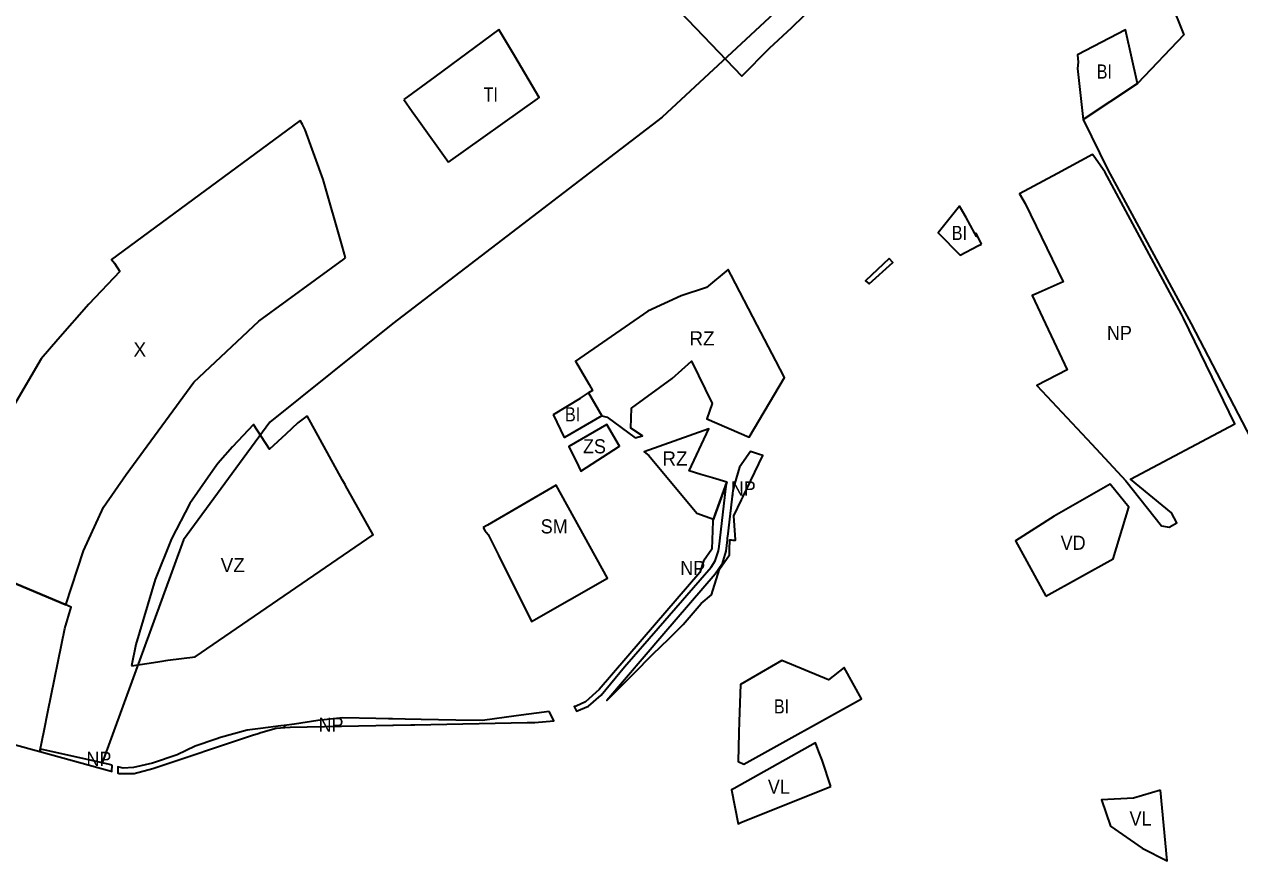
# Model space of a CAD drawing. Extents: x -650276 to -642489, y -1074311 to -1066658.
# Drawn here: x -647227 to -646196, y -1073134 to -1072424 of the extents above; entities that cross this region are included whole.
import ezdxf

# ---------------------------------------------------------------- set-up
doc = ezdxf.new("R2010")
doc.units = 0
doc.header["$LTSCALE"] = 4.8
for name, color, linetype, lineweight in [('18', 7, 'Continuous', 35), ('2', 7, 'Continuous', 35), ('30', 7, 'Continuous', 35), ('34', 7, 'Continuous', 35), ('35', 7, 'Continuous', 35), ('36', 7, 'Continuous', 35), ('41', 7, 'Continuous', 35), ('42', 7, 'Continuous', 35), ('48', 7, 'Continuous', 35), ('51', 7, 'Continuous', 35), ('54', 7, 'Continuous', 35), ('6', 7, 'Continuous', 35), ('61', 7, 'Continuous', 25)]:
    doc.layers.add(name, color=color, linetype=linetype, lineweight=lineweight)
doc.layers.add('62', color=7, linetype='Continuous')
doc.layers.add('63', color=7, linetype='Continuous')

msp = doc.modelspace()

# ---------------------------------------------------------------- linework, layer by layer
at = {"layer": '18'}
msp.add_lwpolyline([(-646837.81, -1072851.3), (-646836.5, -1072853.76), (-646833.67, -1072857.15), (-646824.89, -1072874.66), (-646796.68, -1072930.92), (-646732.28, -1072894.29), (-646775.85, -1072815.39), (-646834.08, -1072849.15)], close=True, dxfattribs=at)
at = {"layer": '2'}
msp.add_line((-646417.787, -1072612.168), (-646414.77, -1072610.61), dxfattribs=at)
for points in [[(-646333.34, -1072461.67), (-646328.45, -1072504.81), (-646282.47, -1072474.34), (-646292.44, -1072428.89), (-646333.33, -1072450.12), (-646332.68, -1072456.19)], [(-646778.2, -1072755.19), (-646755.1, -1072741.28), (-646748.3, -1072737.01), (-646737.05, -1072756.4), (-646768.74, -1072774.78)], [(-646620.38, -1073015.9), (-646620.71, -1073025.49), (-646621.44, -1073049.79), (-646616.55, -1073052.21), (-646516.7, -1072996.65), (-646531.46, -1072970.12), (-646544.68, -1072980.62), (-646584.23, -1072964.22), (-646619.48, -1072984.34)]]:
    msp.add_lwpolyline(points, close=True, dxfattribs=at)
for points in [[(-646420.36, -1072601.78), (-646427.95, -1072588.07), (-646432.57, -1072579.75), (-646433.36, -1072578.45), (-646451.458, -1072601.008), (-646433.024, -1072620.04), (-646417.787, -1072612.168)], [(-646414.77, -1072610.61), (-646419.11, -1072602.03), (-646419.47, -1072601.31), (-646419.02, -1072604.18), (-646420.36, -1072601.78)]]:
    msp.add_lwpolyline(points, dxfattribs=at)
at = {"layer": '30'}
for points in [[(-646824.42, -1072428.58), (-646878.91, -1072468.54), (-646905.18, -1072487.8)], [(-646867.283, -1072540.984), (-646791.569, -1072487.198), (-646790.354, -1072486.136), (-646810.77, -1072451.09), (-646824.42, -1072428.58)], [(-646905.18, -1072487.8), (-646898.1, -1072498.02), (-646893.64, -1072504.45), (-646867.283, -1072540.984)]]:
    msp.add_lwpolyline(points, dxfattribs=at)
at = {"layer": '34'}
msp.add_lwpolyline([(-646542.62, -1073071.1), (-646550.01, -1073048.55), (-646552.79, -1073041.53), (-646555.79, -1073033.92), (-646624.69, -1073072.66), (-646626.967, -1073073.918), (-646621.38, -1073102.66), (-646620.19, -1073102.14), (-646618.56, -1073101.42)], close=True, dxfattribs=at)
msp.add_lwpolyline([(-646542.62, -1073071.1), (-646550.01, -1073048.55), (-646552.79, -1073041.53), (-646555.79, -1073033.92), (-646624.69, -1073072.66), (-646626.967, -1073073.918), (-646621.38, -1073102.66), (-646620.19, -1073102.14), (-646618.56, -1073101.42)], close=True, dxfattribs=at)
for points in [[(-646262.94, -1073074.15), (-646285.77, -1073081.01), (-646312.87, -1073082.4), (-646305.18, -1073104.8), (-646278.38, -1073123.25)], [(-646262.94, -1073074.15), (-646285.77, -1073081.01), (-646312.87, -1073082.4), (-646305.18, -1073104.8), (-646278.38, -1073123.25)], [(-646278.38, -1073123.25), (-646257.09, -1073134.01), (-646262.94, -1073074.15)], [(-646278.38, -1073123.25), (-646257.09, -1073134.01), (-646262.94, -1073074.15)]]:
    msp.add_lwpolyline(points, dxfattribs=at)
at = {"layer": '35'}
msp.add_lwpolyline([(-646360.22, -1072909.57), (-646303.02, -1072877.74), (-646289.63, -1072834.04), (-646305.56, -1072814.43), (-646353.25, -1072841.63), (-646385.86, -1072862.59)], close=True, dxfattribs=at)
at = {"layer": '36'}
for points in [[(-646987.154, -1072756.377), (-646995.02, -1072762.45), (-647005.249, -1072771.938), (-647019.06, -1072784.57), (-647032.7, -1072763.68), (-647050.492, -1072782.771)], [(-646954.7, -1072815.232), (-646957.105, -1072810.92), (-646987.154, -1072756.377)], [(-647050.492, -1072782.771), (-647063.04, -1072796.74), (-647067.22, -1072802.77), (-647086.65, -1072830.76), (-647102.38, -1072860.7), (-647116.33, -1072895.3)], [(-647136.39, -1072968.63), (-647110.32, -1072964.56), (-647107.01, -1072964.04), (-647105.4, -1072963.84), (-647082.36, -1072960.95), (-646931.1, -1072857.55), (-646954.51, -1072815.63), (-646954.7, -1072815.232)], [(-647116.33, -1072895.3), (-647132.47, -1072950.4), (-647136.39, -1072968.63)]]:
    msp.add_lwpolyline(points, dxfattribs=at)
at = {"layer": '41'}
msp.add_lwpolyline([(-646756.92, -1072799.26), (-646754.96, -1072803.29), (-646722.072, -1072782.236), (-646732.76, -1072763.81), (-646765, -1072782.52)], close=True, dxfattribs=at)
at = {"layer": '42'}
msp.add_lwpolyline([(-646696.83, -1072385.81), (-646618.158, -1072468.098), (-646594.606, -1072444.422), (-646575.792, -1072426.789), (-646504.244, -1072357.026)], dxfattribs=at)
at = {"layer": '48'}
msp.add_line((-646779.55, -1073011.68), (-646781.703, -1073007.452), dxfattribs=at)
for points in [[(-646194.19, -1072404.62), (-646254.75, -1072404.25), (-646243.17, -1072432.88), (-646282.47, -1072474.34), (-646328.45, -1072504.81), (-646307.6, -1072547.74), (-646236.97, -1072678.31), (-646171.72, -1072803.51)], [(-646918.156, -1073013.511), (-646928.807, -1073013.313), (-646956.919, -1073012.775), (-646978.077, -1073014.931), (-646997.824, -1073018.092), (-647006.715, -1073019.236), (-647006.15, -1073020.99), (-647001.66, -1073020.72), (-646914.54, -1073019)], [(-646781.703, -1073007.452), (-646809.778, -1073011.019), (-646838.25, -1073014.938), (-646861.07, -1073014.672), (-646890.523, -1073014.073), (-646904.131, -1073013.793), (-646914.796, -1073013.573), (-646918.156, -1073013.511)], [(-646800.44, -1073016.74), (-646793.8, -1073016.61), (-646777.74, -1073015.29), (-646779.55, -1073011.68)], [(-646914.54, -1073019), (-646913.94, -1073018.99), (-646899.22, -1073018.7), (-646895.76, -1073018.63), (-646800.44, -1073016.74)]]:
    msp.add_lwpolyline(points, dxfattribs=at)
for points in [[(-646310.01, -1072549.22), (-646319.56, -1072536.05), (-646320.62, -1072534.6), (-646350.18, -1072550.59), (-646382.41, -1072568.01), (-646377.84, -1072576.29), (-646345.6, -1072642.55), (-646368.51, -1072652.81), (-646371.66, -1072654.2), (-646342.08, -1072717.43), (-646367.72, -1072730.68), (-646321.171, -1072780.535), (-646292.17, -1072811.6), (-646261.97, -1072849.66), (-646255.39, -1072850.83), (-646249.04, -1072847.16), (-646253.56, -1072838.8), (-646288.27, -1072810.22), (-646199.72, -1072763.1), (-646243.32, -1072673.57), (-646245.13, -1072670.2), (-646278.44, -1072608.07)], [(-646493.229, -1072622.74), (-646513.209, -1072641.935), (-646510.28, -1072644.42), (-646490.11, -1072626.15)], [(-646644.059, -1072908.208), (-646637.2, -1072886.57), (-646628.7, -1072874.5), (-646628.58, -1072869.88), (-646628.36, -1072861.71), (-646627.159, -1072861.792), (-646625.96, -1072861.874), (-646625.3, -1072861.919), (-646624.824, -1072861.951), (-646623.67, -1072862.024), (-646623.712, -1072861.37), (-646623.95, -1072857.6), (-646625.02, -1072841.21), (-646618.521, -1072827.719), (-646617.407, -1072825.407), (-646614.07, -1072818.47), (-646600.37, -1072790.04), (-646603.99, -1072788.901), (-646610.86, -1072786.74), (-646620.27, -1072799.95), (-646624.54, -1072814.52), (-646625.91, -1072819.66), (-646630.45, -1072858.93), (-646630.57, -1072859.99), (-646630.76, -1072861.61), (-646631.89, -1072871.33), (-646635.11, -1072882.47), (-646640.96, -1072890.83), (-646684.36, -1072941.43), (-646732.95, -1072998.07), (-646710.3, -1072975.31), (-646693.9, -1072958.84), (-646680.07, -1072945.74), (-646668.09, -1072933.43), (-646652.76, -1072915.66), (-646644.069, -1072908.218), (-646644.061, -1072908.209)], [(-646642.438, -1072844.29), (-646642.939, -1072845.68), (-646643.574, -1072869.57), (-646650.798, -1072879.828), (-646653.846, -1072889.44), (-646692.432, -1072934.135), (-646739.241, -1072988.798), (-646751.061, -1072999.106), (-646758.883, -1073002.885), (-646760.416, -1073003.25), (-646758.44, -1073007.19), (-646748.51, -1073002.74), (-646737.7, -1072993.52), (-646717.7, -1072969.5), (-646689.13, -1072936.62), (-646644.12, -1072884.84), (-646640.92, -1072879.6), (-646637.92, -1072870.91), (-646637.52, -1072867.43), (-646631.85, -1072818.45), (-646631.08, -1072812.68), (-646640.313, -1072838.394), (-646642.404, -1072844.195), (-646642.39, -1072844.2)], [(-647293.317, -1072873.549), (-647293.351, -1072873.533), (-647331.82, -1072854.49), (-647375.92, -1072833.99), (-647387.64, -1072868.69), (-647392.96, -1072918.277), (-647394.87, -1072936.08), (-647388.62, -1072948.03), (-647395.47, -1072993.25), (-647367.45, -1073002.47), (-647353.78, -1073003.1), (-647213.99, -1073041.449), (-647210.396, -1073023.593), (-647207.176, -1073007.598), (-647192.93, -1072936.82), (-647187.445, -1072918.804), (-647192.718, -1072916.582), (-647282.31, -1072878.82), (-647284.75, -1072877.79)], [(-647006.715, -1073019.236), (-647009.402, -1073019.582), (-647026.763, -1073021.811), (-647037.971, -1073023.24), (-647060.677, -1073029.351), (-647064.784, -1073030.747), (-647082.267, -1073036.684), (-647097.466, -1073044.268), (-647118.513, -1073051.327), (-647134.596, -1073054.974), (-647143.312, -1073055.421), (-647147.85, -1073054.204), (-647147.91, -1073059.64), (-647147.43, -1073059.78), (-647147.17, -1073059.97), (-647134.03, -1073059.94), (-647118.27, -1073055.88), (-647033.44, -1073027.43), (-647028.91, -1073025.91), (-647026.54, -1073025.11), (-647013.4, -1073021.42), (-647006.15, -1073020.99)], [(-647152.621, -1073052.925), (-647154.999, -1073052.287), (-647161.068, -1073050.946), (-647161.068, -1073050.946), (-647161.068, -1073050.946), (-647213.218, -1073039.42), (-647213.562, -1073039.322), (-647213.99, -1073041.449), (-647153.44, -1073058.06), (-647152.96, -1073058.19)]]:
    msp.add_lwpolyline(points, close=True, dxfattribs=at)
at = {"layer": '51'}
for points in [[(-646993.05, -1072505.68), (-646994.2, -1072506.52), (-647153.2, -1072623.68), (-647150.75, -1072626.84), (-647146.21, -1072634.02)], [(-646954.617, -1072622.388), (-646957.5, -1072612.09), (-646973.68, -1072555.68), (-646989.01, -1072513.62), (-646991.24, -1072509.24), (-646993.05, -1072505.68)], [(-647192.069, -1072916.856), (-647177.144, -1072871.095), (-647160.08, -1072833.974), (-647140.764, -1072806.081), (-647083.498, -1072727.769), (-647028.234, -1072676.101), (-646956.061, -1072623.348), (-646954.617, -1072622.388)], [(-647146.21, -1072634.02), (-647172.36, -1072661.69), (-647198.77, -1072691.71), (-647212.92, -1072708.05)], [(-647212.92, -1072708.05), (-647236.54, -1072748.09), (-647252.29, -1072783.24), (-647263.58, -1072809.97), (-647284.75, -1072877.79), (-647282.31, -1072878.82), (-647192.718, -1072916.582), (-647192.069, -1072916.856)]]:
    msp.add_lwpolyline(points, dxfattribs=at)
at = {"layer": '54'}
msp.add_lwpolyline([(-646516, -1072345), (-646685.823, -1072502.987), (-646914.429, -1072678.004), (-647018.969, -1072761.795), (-647092.194, -1072861.614), (-647161.068, -1073050.946)], dxfattribs=at)
at = {"layer": '6'}
for points in [[(-646737.05, -1072756.4), (-646732.5, -1072757.63), (-646708.65, -1072775.02), (-646702.45, -1072773.39), (-646712.46, -1072766.76), (-646711.79, -1072750.02), (-646677.39, -1072724.85), (-646660.89, -1072709.97), (-646643.36, -1072746.04), (-646647.93, -1072759.01), (-646612.11, -1072774.56), (-646581.92, -1072723.91), (-646589.37, -1072709.83), (-646605.23, -1072679.37), (-646627.32, -1072636.95), (-646629.86, -1072632.07), (-646648.27, -1072647.48), (-646669.6, -1072654.53), (-646697.89, -1072667.65)], [(-646697.89, -1072667.65), (-646732.95, -1072691.68), (-646759.491, -1072709.878), (-646757.5, -1072713.3), (-646747.87, -1072729.85), (-646744.94, -1072734.88), (-646748.3, -1072737.01), (-646737.05, -1072756.4)], [(-646653.02, -1072806.07), (-646663.07, -1072803.04), (-646663.07, -1072803.04), (-646646.12, -1072767.32), (-646646.31, -1072767.388), (-646701.12, -1072787.08), (-646697.09, -1072790.03), (-646656.36, -1072839.08)], [(-646656.36, -1072839.08), (-646642.404, -1072844.195), (-646631.08, -1072812.68), (-646643.01, -1072809.08), (-646651.11, -1072806.64), (-646653.02, -1072806.07)]]:
    msp.add_lwpolyline(points, dxfattribs=at)

# ---------------------------------------------------------------- texts
at = {"layer": '61'}
msp.add_text('X', height=12, dxfattribs=at).set_placement((-647134.58, -1072706.109))
at = {"layer": '62'}
for s, width, p in [('BI', 0.85, (-646317, -1072470.167)), ('TI', 0.85, (-646837.377, -1072489.619)), ('BI', 0.85, (-646440, -1072607.167)), ('NP', 0.95, (-646308.335, -1072692.048)), ('BI', 0.85, (-646768.325, -1072761.133)), ('ZS', 0.95, (-646753.085, -1072788.28)), ('NP', 0.95, (-646627.575, -1072824.064)), ('SM', 0.95, (-646788.938, -1072856.245)), ('VD', 0.95, (-646347.605, -1072870.155)), ('NP', 0.95, (-646670.505, -1072891.594)), ('BI', 0.85, (-646590.991, -1073009.043)), ('NP', 0.95, (-646977.505, -1073024.594)), ('NP', 0.95, (-647174.505, -1073053.594)), ('VL', 0.95, (-646596.107, -1073077.218)), ('VL', 0.95, (-646289.107, -1073104.218))]:
    msp.add_text(s, height=12, dxfattribs=dict(at, width=width)).set_placement(p)
for p in [(-646662.725, -1072696.633), (-646685.725, -1072798.633)]:
    msp.add_text('RZ', height=12, dxfattribs=at).set_placement(p)
at = {"layer": '63'}
msp.add_text('VZ', height=12, dxfattribs=at).set_placement((-647060.598, -1072889.069))

doc.saveas('drawing.dxf')
